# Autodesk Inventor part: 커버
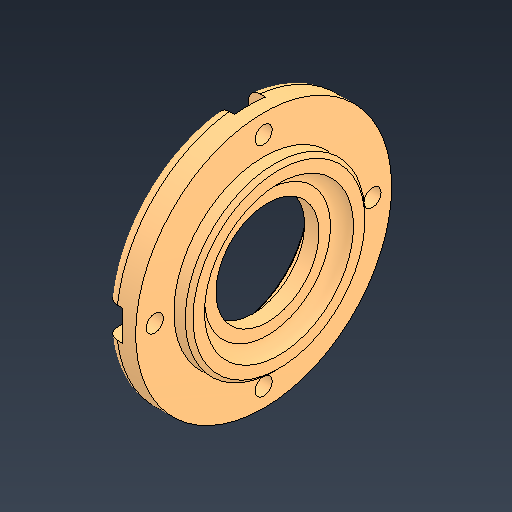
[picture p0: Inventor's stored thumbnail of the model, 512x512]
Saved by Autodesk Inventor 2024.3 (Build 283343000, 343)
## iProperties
Created: 2025-07
Part Number: 커버
Material: 알루미늄 6061
Document SubType Name: Modeling
Designer: user
Density: 2.7 g/cm^3
Appearance: 기본값
Sending System: Autodesk Inventor 2026
Preprocessor: ST-DEVELOPER v20.1
Author: jhkim
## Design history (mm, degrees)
feature "솔리드1"
node "솔리드2"
